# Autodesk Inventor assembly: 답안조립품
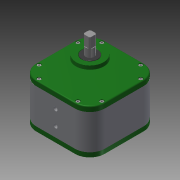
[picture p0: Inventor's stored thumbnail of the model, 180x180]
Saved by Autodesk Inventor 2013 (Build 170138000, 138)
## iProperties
Created: 2017-11
Part Number: 답안조립품
Document SubType Name: Assembly
Designer: Administrator
Author: Administrator
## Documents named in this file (11)
- C:\Users\Administrator\Desktop\371108V1002\답안조립품.iam
- C:\Users\Administrator\Desktop\371108V1002\본체.ipt
- C:\Users\Administrator\Desktop\371108V1002\뒤커버.ipt
- C:\Users\Administrator\Desktop\371108V1002\메인축.ipt
- C:\Users\Administrator\Desktop\371108V1002\베어링 608.ipt
- C:\Users\Administrator\Desktop\371108V1002\베어링 6003.ipt
- C:\Users\Administrator\Desktop\371108V1002\볼트 M4.ipt
- C:\Users\Administrator\Desktop\371108V1002\서브축.ipt
- C:\Users\Administrator\Desktop\371108V1002\앞커버.ipt
- C:\Users\Administrator\Desktop\371108V1002\오일실 8 22 7.ipt
- C:\Users\Administrator\Desktop\371108V1002\오일실 17 32 8.ipt
